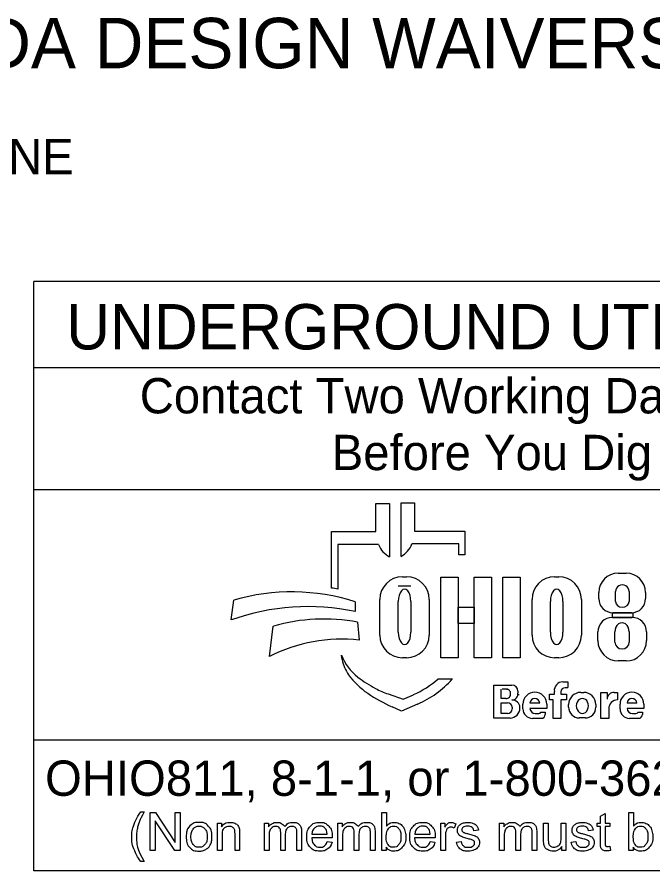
# Model space of a CAD drawing. Extents: x 0 to 34, y 0 to 22.
# Drawn here: x 2.311 to 4.831, y 2.143 to 5.529 of the extents above; entities that cross this region are included whole.
import ezdxf

# ---------------------------------------------------------------- set-up
doc = ezdxf.new("R2010")
doc.units = 0
doc.layers.add('SH_Data', color=7, linetype='Continuous')
doc.layers.add('SH_Text', color=7, linetype='Continuous')

msp = doc.modelspace()

# ---------------------------------------------------------------- linework, layer by layer
at = {"layer": 'SH_Data'}
for p, q in [((2.3775, 2.1428), (2.3775, 4.4803)), ((6.6275, 4.4803), (2.3775, 4.4803)), ((2.3775, 4.1387), (6.6275, 4.1387)), ((2.3775, 3.6553), (6.6275, 3.6553)), ((6.6275, 2.6607), (2.3775, 2.6607)), ((6.6275, 2.1428), (2.3775, 2.1428))]:
    msp.add_line(p, q, dxfattribs=at)
at = {"layer": 'SH_Text'}
for p, q in [((3.7335, 3.4883), (3.7335, 3.5998)), ((3.7335, 3.5998), (3.7872, 3.5998)), ((3.7872, 3.5998), (3.7872, 3.3877)), ((3.8329, 3.39), (3.8329, 3.6021)), ((3.8329, 3.6021), (3.8865, 3.6021)), ((3.8865, 3.6021), (3.8865, 3.4906)), ((3.5576, 3.2644), (3.5576, 3.4883)), ((3.5576, 3.4883), (3.7335, 3.4883)), ((3.8865, 3.4906), (4.0857, 3.4906)), ((4.0857, 3.4906), (4.0857, 3.3968)), ((3.5828, 3.4369), (3.5828, 3.26)), ((3.7439, 3.4369), (3.5828, 3.4369)), ((4.0625, 3.4392), (3.8761, 3.4392)), ((4.0625, 3.3968), (4.0625, 3.4392)), ((4.0857, 3.3968), (4.0625, 3.3968)), ((4.6931, 3.3231), (4.7258, 3.3231)), ((3.8385, 3.3091), (3.8551, 3.3091)), ((4.4416, 3.3091), (4.4581, 3.3091)), ((3.8718, 3.2721), (3.822, 3.2721)), ((4.683, 3.2111), (4.683, 3.2504)), ((4.7371, 3.2504), (4.7371, 3.2111)), ((3.7491, 3.0776), (3.7491, 3.2196)), ((3.9445, 3.2196), (3.9445, 3.0776)), ((4.3521, 3.0776), (4.3521, 3.2196)), ((4.5476, 3.2196), (4.5476, 3.0776)), ((4.6168, 3.2225), (4.6168, 3.2468)), ((4.8022, 3.2468), (4.8022, 3.2225)), ((3.1602, 3.1381), (3.1696, 3.2162)), ((3.6509, 3.2097), (3.6509, 3.1709)), ((3.822, 3.089), (3.822, 3.2114)), ((3.8718, 3.2114), (3.8718, 3.089)), ((4.425, 3.089), (4.425, 3.2114)), ((4.4748, 3.2114), (4.4748, 3.089)), ((4.7462, 3.1665), (4.6728, 3.1665)), ((3.6608, 3.1291), (3.6671, 3.0582)), ((4.671, 3.1482), (4.7483, 3.1482)), ((3.312, 2.9936), (3.3267, 3.1137)), ((4.6131, 3.0563), (4.6131, 3.0903)), ((4.6806, 3.0503), (4.6806, 3.0912)), ((4.7374, 3.0912), (4.7374, 3.0503)), ((4.8062, 3.0903), (4.8062, 3.0563)), ((3.5997, 2.9807), (3.5967, 2.9986)), ((3.8551, 2.9882), (3.8385, 2.9882)), ((4.4581, 2.9882), (4.4416, 2.9882)), ((4.7252, 2.9753), (4.6941, 2.9753)), ((3.98, 2.9048), (4.0375, 2.9048)), ((4.2013, 2.749), (4.2013, 2.8798)), ((4.2013, 2.8798), (4.2725, 2.8798)), ((4.4739, 2.8926), (4.4934, 2.8926)), ((4.4934, 2.8926), (4.4934, 2.8696)), ((3.7816, 2.8444), (3.841, 2.8239)), ((4.2293, 2.8263), (4.2293, 2.8632)), ((4.2545, 2.8632), (4.2332, 2.8632)), ((4.2963, 2.856), (4.2963, 2.8481)), ((4.4213, 2.8212), (4.4213, 2.8442)), ((4.4213, 2.8442), (4.4406, 2.8442)), ((4.4406, 2.8442), (4.4406, 2.8546)), ((4.4667, 2.8526), (4.4667, 2.8442)), ((4.4667, 2.8442), (4.4883, 2.8442)), ((4.4934, 2.8691), (4.4832, 2.8691)), ((4.4883, 2.8442), (4.4883, 2.8212)), ((4.5451, 2.8508), (4.5573, 2.8508)), ((4.6254, 2.7478), (4.6254, 2.8505)), ((4.6254, 2.8505), (4.6499, 2.8505)), ((4.6499, 2.8505), (4.6499, 2.8237)), ((4.6772, 2.8505), (4.691, 2.8505)), ((4.691, 2.8505), (4.691, 2.8209)), ((3.841, 2.8239), (3.8821, 2.8417)), ((4.2487, 2.8263), (4.2293, 2.8263)), ((4.4362, 2.8212), (4.4213, 2.8212)), ((4.4362, 2.7478), (4.4362, 2.8212)), ((4.4883, 2.8212), (4.4667, 2.8212)), ((4.4667, 2.8212), (4.4667, 2.7478)), ((3.835, 2.7769), (3.7976, 2.7934)), ((3.8983, 2.8044), (3.835, 2.7769)), ((4.2293, 2.7669), (4.2293, 2.8097)), ((4.2293, 2.8097), (4.2548, 2.8097)), ((4.2729, 2.7916), (4.2729, 2.7853)), ((4.3043, 2.7887), (4.3043, 2.7884)), ((4.3159, 2.7858), (4.3159, 2.8042)), ((4.3824, 2.8082), (4.3439, 2.8082)), ((4.4104, 2.7866), (4.344, 2.7866)), ((4.4104, 2.8042), (4.4104, 2.7866)), ((4.4973, 2.7922), (4.4973, 2.8029)), ((4.6051, 2.8029), (4.6051, 2.7922)), ((4.6559, 2.786), (4.6559, 2.7478)), ((4.7008, 2.7858), (4.7008, 2.8042)), ((4.7674, 2.8082), (4.7288, 2.8082)), ((4.7953, 2.7866), (4.7289, 2.7866)), ((4.7953, 2.8042), (4.7953, 2.7866)), ((4.265, 2.749), (4.2013, 2.749)), ((4.2546, 2.7669), (4.2293, 2.7669)), ((4.3892, 2.7478), (4.3538, 2.7478)), ((4.3649, 2.7673), (4.379, 2.7673)), ((4.3876, 2.7729), (4.4045, 2.7729)), ((4.4045, 2.7729), (4.4045, 2.7631)), ((4.4667, 2.7478), (4.4362, 2.7478)), ((4.5623, 2.7494), (4.5401, 2.7494)), ((4.6559, 2.7478), (4.6254, 2.7478)), ((4.7742, 2.7478), (4.7388, 2.7478)), ((4.7498, 2.7673), (4.7639, 2.7673)), ((4.7725, 2.7729), (4.7894, 2.7729)), ((4.7894, 2.7729), (4.7894, 2.7631))]:
    msp.add_line(p, q, dxfattribs=at)
for points in [[(3.991, 3.3081), (4.0589, 3.3081), (4.0589, 2.9881), (3.991, 2.9881)], [(4.1231, 3.3081), (4.1911, 3.3081), (4.1911, 2.9881), (4.1231, 2.9881)], [(4.2364, 3.3081), (4.3052, 3.3081), (4.3052, 2.9881), (4.2364, 2.9881)], [(4.0589, 3.1882), (4.1231, 3.1882), (4.1231, 3.1242), (4.0589, 3.1242)], [(4.6706, 3.1665), (4.7523, 3.1665), (4.7523, 3.1481), (4.6706, 3.1481)]]:
    msp.add_lwpolyline(points, close=True, dxfattribs=at)
for points in [[(2.8021, 2.3766), (2.8153, 2.3766)], [(2.8389, 2.2239), (2.8389, 2.3741), (2.8592, 2.3741), (2.9382, 2.2561), (2.9382, 2.3741), (2.9572, 2.3741), (2.9572, 2.2239), (2.9369, 2.2239), (2.8579, 2.3419), (2.8579, 2.2239), (2.8389, 2.2239)], [(3.7743, 2.2239), (3.7573, 2.2239), (3.7573, 2.3741), (3.7757, 2.3741), (3.7757, 2.3206)], [(4.6233, 2.2558), (4.6233, 2.3185), (4.6097, 2.3185), (4.6097, 2.3328), (4.6233, 2.3328), (4.6233, 2.3597), (4.6417, 2.3708), (4.6417, 2.3328), (4.6601, 2.3328), (4.6601, 2.3185), (4.6417, 2.3185), (4.6417, 2.2547)], [(4.7534, 2.2239), (4.7363, 2.2239), (4.7363, 2.3741), (4.7548, 2.3741), (4.7548, 2.3206)], [(3.1048, 2.2239), (3.1048, 2.3328), (3.1214, 2.3328), (3.1214, 2.3173)], [(3.2912, 2.2239), (3.2912, 2.3328), (3.3077, 2.3328), (3.3077, 2.3174)], [(3.5826, 2.2239), (3.5826, 2.3328), (3.5991, 2.3328), (3.5991, 2.3174)], [(3.9904, 2.2239), (3.9904, 2.3328), (4.007, 2.3328), (4.007, 2.3163)], [(4.0495, 2.3293), (4.043, 2.3122)], [(4.1394, 2.3046), (4.1213, 2.3022)], [(4.2236, 2.2239), (4.2236, 2.3328), (4.2401, 2.3328), (4.2401, 2.3174)], [(4.3979, 2.2654), (4.3979, 2.3328), (4.4164, 2.3328), (4.4164, 2.2724)], [(4.4676, 2.2745), (4.4676, 2.3328), (4.4861, 2.3328), (4.4861, 2.2239), (4.4696, 2.2239)], [(4.594, 2.3046), (4.5759, 2.3022)], [(3.1233, 2.2833), (3.1233, 2.2239), (3.1048, 2.2239)], [(3.1932, 2.2908), (3.1932, 2.2239), (3.1748, 2.2239), (3.1748, 2.2901)], [(3.3097, 2.2803), (3.3097, 2.2239), (3.2912, 2.2239)], [(3.3743, 2.2871), (3.3743, 2.2239), (3.3559, 2.2239), (3.3559, 2.2946)], [(3.4388, 2.2986), (3.4388, 2.2239), (3.4203, 2.2239), (3.4203, 2.2924)], [(3.56, 2.2736), (3.4788, 2.2736)], [(3.4799, 2.2887), (3.5406, 2.2887)], [(3.601, 2.2803), (3.601, 2.2239), (3.5826, 2.2239)], [(3.6657, 2.2871), (3.6657, 2.2239), (3.6473, 2.2239), (3.6473, 2.2946)], [(3.7301, 2.2986), (3.7301, 2.2239), (3.7117, 2.2239), (3.7117, 2.2924)], [(3.968, 2.2736), (3.8868, 2.2736)], [(3.8879, 2.2887), (3.9486, 2.2887)], [(4.0088, 2.2809), (4.0088, 2.2239), (3.9904, 2.2239)], [(4.242, 2.2803), (4.242, 2.2239), (4.2236, 2.2239)], [(4.3067, 2.2871), (4.3067, 2.2239), (4.2883, 2.2239), (4.2883, 2.2946)], [(4.3711, 2.2986), (4.3711, 2.2239), (4.3527, 2.2239), (4.3527, 2.2924)], [(3.5404, 2.2591), (3.5595, 2.2567)], [(3.7743, 2.2375), (3.7743, 2.2239)], [(3.9484, 2.2591), (3.9675, 2.2567)], [(4.053, 2.2564), (4.0712, 2.2593)], [(4.4696, 2.2239), (4.4696, 2.24)], [(4.5076, 2.2564), (4.5258, 2.2593)], [(4.6601, 2.2404), (4.6628, 2.2241)], [(4.7534, 2.2375), (4.7534, 2.2239)], [(2.8153, 2.1798), (2.8021, 2.1798)]]:
    msp.add_lwpolyline(points, dxfattribs=at)
for centre, radius, start, end in [((3.8353, 3.4736), 0.0985, 201.9296, 240.7469), ((3.7847, 3.476), 0.0985, 299.2531, 338.0704), ((4.6931, 3.2468), 0.0763, 90, 180), ((4.7258, 3.2468), 0.0763, 0, 90), ((3.8385, 3.2196), 0.0895, 90, 180), ((3.8551, 3.2196), 0.0895, 0, 90), ((4.4416, 3.2196), 0.0895, 90, 180), ((4.4581, 3.2196), 0.0895, 0, 90), ((3.4295, 2.4554), 0.8191, 79.2074, 81.0007), ((3.3997, 2.4302), 0.8191, 72.1402, 106.3144), ((4.6728, 3.2225), 0.056, 180, 270), ((4.7462, 3.2225), 0.056, 270, 0), ((3.4628, 2.2991), 0.8919, 77.8238, 109.8274), ((3.5267, 2.4094), 0.7322, 79.44, 105.8467), ((4.671, 3.0903), 0.0579, 90, 180), ((4.7483, 3.0903), 0.0579, 0, 90), ((3.5987, 2.4262), 0.6357, 83.8248, 116.8021), ((3.8385, 3.0776), 0.0895, 180, 270), ((3.8551, 3.0776), 0.0895, 270, 0), ((4.4416, 3.0776), 0.0895, 180, 270), ((4.4581, 3.0776), 0.0895, 270, 0), ((4.6941, 3.0563), 0.081, 180, 270), ((4.7252, 3.0563), 0.081, 270, 0), ((3.7841, 3.0707), 0.2008, 201.0457, 232.5314), ((3.741, 3.0048), 0.1433, 189.6817, 216.0884), ((3.8747, 3.1022), 0.3088, 216.0884, 235.7167), ((3.9766, 3.3219), 0.5173, 232.5314, 241.794), ((3.7387, 3.1722), 0.3602, 293.4582, 312.0712), ((3.7387, 3.1722), 0.401, 293.4582, 317.8286), ((4.2725, 2.856), 0.0238, 0, 90), ((4.4739, 2.859), 0.0335, 90, 187.5187), ((4.0412, 3.3465), 0.6044, 235.7167, 246.2325), ((3.8914, 3.1631), 0.3371, 241.794, 250.9821), ((4.2487, 2.845), 0.0187, 270, 2.0582), ((4.2505, 2.8463), 0.0169, 357.8325, 90), ((4.2721, 2.8453), 0.0243, 270, 6.6529), ((4.3631, 2.8042), 0.0473, 0, 180), ((4.4832, 2.8526), 0.0165, 90, 180), ((4.5451, 2.8029), 0.0478, 90, 180), ((4.5573, 2.8029), 0.0478, 0, 90), ((4.6768, 2.8237), 0.0269, 89.2449, 180), ((4.7481, 2.8042), 0.0473, 0, 180), ((4.2722, 2.7889), 0.0321, 4.0748, 90), ((4.2827, 2.8438), 0.0175, 347.4023, 0), ((4.3632, 2.8072), 0.0193, 2.9632, 177.0368), ((4.6908, 2.786), 0.0349, 89.6033, 180), ((4.7481, 2.8072), 0.0193, 2.9632, 177.0368), ((4.2546, 2.7853), 0.0184, 270, 0), ((4.2548, 2.7916), 0.0181, 0, 90), ((4.265, 2.7884), 0.0393, 270, 0), ((4.2714, 2.7887), 0.033, 0, 11.7502), ((4.3538, 2.7858), 0.038, 180, 270), ((4.3649, 2.7883), 0.021, 184.827, 270), ((4.5401, 2.7922), 0.0428, 180, 270), ((4.5623, 2.7922), 0.0428, 270, 0), ((4.7388, 2.7858), 0.038, 180, 270), ((4.7498, 2.7883), 0.021, 184.827, 270), ((4.379, 2.7767), 0.00938, 270, 335.9979), ((4.3892, 2.7631), 0.0152, 270, 0), ((4.7639, 2.7767), 0.00938, 270, 335.9979), ((4.7742, 2.7631), 0.0152, 270, 0)]:
    msp.add_arc(centre, radius, start, end, dxfattribs=at)
for centre, major_axis, ratio, start_param, end_param in [((3.8469, 3.2114), (0, 0.0484), 0.514403, 4.712389, 7.853982), ((4.4499, 3.2114), (0, 0.0484), 0.514403, 4.712389, 7.853982), ((4.71, 3.2504), (0.0271, 0), 0.969373, 0, 3.141593), ((4.71, 3.2111), (0.0271, 0), 0.818453, 3.141593, 6.283185), ((4.709, 3.0912), (0, 0.0358), 0.794529, 4.712389, 7.853982), ((3.8469, 3.089), (0, 0.0484), 0.514403, 1.570796, 4.712389), ((4.4499, 3.089), (0, 0.0484), 0.514403, 1.570796, 4.712389), ((4.709, 3.0503), (0.0284, 0), 0.959837, 3.141593, 6.283185), ((4.5517, 2.7976), (0, 0.029), 0.832186, 4.712389, 7.853982), ((4.5517, 2.7976), (0, 0.0302), 0.797287, 1.570796, 4.712389)]:
    msp.add_ellipse(centre, major_axis=major_axis, ratio=ratio, start_param=start_param, end_param=end_param, dxfattribs=at)
for points in [[(2.8021, 2.1798), (2.7869, 2.199), (2.7763, 2.2248), (2.7657, 2.2506), (2.7657, 2.2783), (2.7657, 2.3026), (2.7736, 2.325), (2.7829, 2.3509), (2.8021, 2.3766)], [(2.8153, 2.3766), (2.8029, 2.3553), (2.7989, 2.3462), (2.7927, 2.332), (2.7891, 2.3167), (2.7847, 2.2975), (2.7847, 2.2782), (2.7847, 2.2289), (2.8153, 2.1798)], [(2.9814, 2.2783), (2.9814, 2.3085), (2.9981, 2.3231), (3.0122, 2.3352), (3.0323, 2.3352), (3.0547, 2.3352), (3.069, 2.3205), (3.0832, 2.3058), (3.0832, 2.2799), (3.0832, 2.2589), (3.0769, 2.2469), (3.0706, 2.2348), (3.0586, 2.2282), (3.0466, 2.2215), (3.0323, 2.2215), (3.0095, 2.2215), (2.9954, 2.2362), (2.9814, 2.2508), (2.9814, 2.2783)], [(3.0003, 2.2783), (3.0003, 2.2574), (3.0094, 2.247), (3.0185, 2.2366), (3.0323, 2.2366), (3.046, 2.2366), (3.0551, 2.2471), (3.0642, 2.2575), (3.0642, 2.279), (3.0642, 2.2991), (3.0551, 2.3095), (3.0459, 2.3199), (3.0323, 2.3199), (3.0185, 2.3199), (3.0094, 2.3096), (3.0003, 2.2992), (3.0003, 2.2783)], [(3.1214, 2.3173), (3.1334, 2.3352), (3.156, 2.3352), (3.1659, 2.3352), (3.1741, 2.3316), (3.1823, 2.3281), (3.1864, 2.3224), (3.1905, 2.3166), (3.1922, 2.3087), (3.1932, 2.3036), (3.1932, 2.2908)], [(3.1748, 2.2901), (3.1748, 2.3013), (3.1726, 2.3069), (3.1705, 2.3125), (3.165, 2.3158), (3.1595, 2.3191), (3.1521, 2.3191), (3.1404, 2.3191), (3.1318, 2.3117), (3.1233, 2.3042), (3.1233, 2.2833)], [(3.3077, 2.3174), (3.3128, 2.3254), (3.3214, 2.3303), (3.3299, 2.3352), (3.3407, 2.3352), (3.3528, 2.3352), (3.3606, 2.3301), (3.3683, 2.3251), (3.3715, 2.3161), (3.3844, 2.3352), (3.4051, 2.3352), (3.4213, 2.3352), (3.43, 2.3262), (3.4388, 2.3172), (3.4388, 2.2986)], [(3.3559, 2.2946), (3.3559, 2.3069), (3.3514, 2.313), (3.3469, 2.3191), (3.3366, 2.3191), (3.3288, 2.3191), (3.3222, 2.315), (3.3156, 2.311), (3.3126, 2.3031), (3.3097, 2.2952), (3.3097, 2.2803)], [(3.4203, 2.2924), (3.4203, 2.3035), (3.4185, 2.3083), (3.4168, 2.3132), (3.412, 2.3162), (3.4073, 2.3191), (3.401, 2.3191), (3.3895, 2.3191), (3.3819, 2.3115), (3.3743, 2.3039), (3.3743, 2.2871)], [(3.5595, 2.2567), (3.555, 2.24), (3.5428, 2.2307), (3.5306, 2.2215), (3.5117, 2.2215), (3.4878, 2.2215), (3.4738, 2.2362), (3.4598, 2.2509), (3.4598, 2.2774), (3.4598, 2.3049), (3.474, 2.32), (3.4881, 2.3352), (3.5106, 2.3352), (3.5324, 2.3352), (3.5463, 2.3203), (3.5601, 2.3055), (3.5601, 2.2785), (3.5601, 2.2769), (3.56, 2.2736)], [(3.5406, 2.2887), (3.5394, 2.3025), (3.5337, 2.3094), (3.5249, 2.3201), (3.5108, 2.3201), (3.4981, 2.3201), (3.4894, 2.3115), (3.4808, 2.303), (3.4799, 2.2887)], [(3.5991, 2.3174), (3.6042, 2.3254), (3.6127, 2.3303), (3.6212, 2.3352), (3.6321, 2.3352), (3.6442, 2.3352), (3.6519, 2.3301), (3.6597, 2.3251), (3.6628, 2.3161), (3.6758, 2.3352), (3.6965, 2.3352), (3.7127, 2.3352), (3.7214, 2.3262), (3.7301, 2.3172), (3.7301, 2.2986)], [(3.6473, 2.2946), (3.6473, 2.3069), (3.6428, 2.313), (3.6383, 2.3191), (3.628, 2.3191), (3.6202, 2.3191), (3.6136, 2.315), (3.607, 2.311), (3.604, 2.3031), (3.601, 2.2952), (3.601, 2.2803)], [(3.7117, 2.2924), (3.7117, 2.3035), (3.7099, 2.3083), (3.7081, 2.3132), (3.7034, 2.3162), (3.6987, 2.3191), (3.6923, 2.3191), (3.6809, 2.3191), (3.6733, 2.3115), (3.6657, 2.3039), (3.6657, 2.2871)], [(3.7741, 2.2792), (3.7741, 2.2596), (3.7794, 2.2509), (3.7881, 2.2366), (3.8029, 2.2366), (3.815, 2.2366), (3.8238, 2.2471), (3.8326, 2.2576), (3.8326, 2.2784), (3.8326, 2.2998), (3.8241, 2.3099), (3.8157, 2.3201), (3.8038, 2.3201), (3.7917, 2.3201), (3.7829, 2.3096), (3.7741, 2.299), (3.7741, 2.2792)], [(3.7757, 2.3206), (3.7874, 2.3352), (3.8055, 2.3352), (3.8155, 2.3352), (3.8245, 2.3311), (3.8335, 2.3271), (3.8392, 2.3198), (3.845, 2.3124), (3.8483, 2.3021), (3.8516, 2.2918), (3.8516, 2.28), (3.8516, 2.252), (3.8378, 2.2368), (3.8239, 2.2215), (3.8046, 2.2215), (3.7853, 2.2215), (3.7743, 2.2375)], [(3.9675, 2.2567), (3.963, 2.24), (3.9508, 2.2307), (3.9386, 2.2215), (3.9196, 2.2215), (3.8958, 2.2215), (3.8818, 2.2362), (3.8678, 2.2509), (3.8678, 2.2774), (3.8678, 2.3049), (3.882, 2.32), (3.8961, 2.3352), (3.9186, 2.3352), (3.9404, 2.3352), (3.9543, 2.3203), (3.9681, 2.3055), (3.9681, 2.2785), (3.9681, 2.2769), (3.968, 2.2736)], [(3.9486, 2.2887), (3.9474, 2.3025), (3.9417, 2.3094), (3.9328, 2.3201), (3.9188, 2.3201), (3.9061, 2.3201), (3.8974, 2.3115), (3.8888, 2.303), (3.8879, 2.2887)], [(4.007, 2.3163), (4.0133, 2.3278), (4.0187, 2.3315), (4.0241, 2.3352), (4.0305, 2.3352), (4.0398, 2.3352), (4.0495, 2.3293)], [(4.043, 2.3122), (4.0363, 2.3162), (4.0295, 2.3162), (4.0235, 2.3162), (4.0187, 2.3125), (4.0139, 2.3089), (4.0119, 2.3024), (4.0088, 2.2926), (4.0088, 2.2809)], [(4.1213, 2.3022), (4.1201, 2.3106), (4.1142, 2.3153), (4.1083, 2.3201), (4.0975, 2.3201), (4.0848, 2.3201), (4.0794, 2.3159), (4.0739, 2.3116), (4.0739, 2.306), (4.0739, 2.3024), (4.0762, 2.2995), (4.0785, 2.2966), (4.0833, 2.2946), (4.086, 2.2936), (4.0996, 2.2899), (4.1192, 2.2847), (4.1269, 2.2813), (4.1347, 2.278), (4.1391, 2.2717), (4.1435, 2.2653), (4.1435, 2.2559), (4.1435, 2.2467), (4.1381, 2.2386), (4.1327, 2.2304), (4.1226, 2.226), (4.1124, 2.2215), (4.0996, 2.2215), (4.0784, 2.2215), (4.0672, 2.2303), (4.0561, 2.2391), (4.053, 2.2564)], [(4.0712, 2.2593), (4.0727, 2.2483), (4.0798, 2.2425), (4.0868, 2.2366), (4.0995, 2.2366), (4.1122, 2.2366), (4.1184, 2.2418), (4.1245, 2.247), (4.1245, 2.254), (4.1245, 2.2602), (4.1191, 2.2638), (4.1153, 2.2663), (4.1002, 2.2701), (4.0799, 2.2752), (4.072, 2.2789), (4.0642, 2.2827), (4.0601, 2.2893), (4.0561, 2.2959), (4.0561, 2.3038), (4.0561, 2.3111), (4.0594, 2.3173), (4.0628, 2.3235), (4.0685, 2.3276), (4.0728, 2.3308), (4.0803, 2.333), (4.0877, 2.3352), (4.0962, 2.3352), (4.109, 2.3352), (4.1187, 2.3315), (4.1284, 2.3278), (4.133, 2.3215), (4.1377, 2.3152), (4.1394, 2.3046)], [(4.2401, 2.3174), (4.2452, 2.3254), (4.2537, 2.3303), (4.2622, 2.3352), (4.2731, 2.3352), (4.2852, 2.3352), (4.2929, 2.3301), (4.3007, 2.3251), (4.3038, 2.3161), (4.3168, 2.3352), (4.3375, 2.3352), (4.3537, 2.3352), (4.3624, 2.3262), (4.3711, 2.3172), (4.3711, 2.2986)], [(4.2883, 2.2946), (4.2883, 2.3069), (4.2838, 2.313), (4.2793, 2.3191), (4.269, 2.3191), (4.2612, 2.3191), (4.2546, 2.315), (4.248, 2.311), (4.245, 2.3031), (4.242, 2.2952), (4.242, 2.2803)], [(4.3527, 2.2924), (4.3527, 2.3035), (4.3509, 2.3083), (4.3491, 2.3132), (4.3444, 2.3162), (4.3397, 2.3191), (4.3333, 2.3191), (4.3219, 2.3191), (4.3143, 2.3115), (4.3067, 2.3039), (4.3067, 2.2871)], [(4.5759, 2.3022), (4.5747, 2.3106), (4.5688, 2.3153), (4.5629, 2.3201), (4.5521, 2.3201), (4.5394, 2.3201), (4.5339, 2.3159), (4.5285, 2.3116), (4.5285, 2.306), (4.5285, 2.3024), (4.5308, 2.2995), (4.533, 2.2966), (4.5378, 2.2946), (4.5406, 2.2936), (4.5542, 2.2899), (4.5737, 2.2847), (4.5815, 2.2813), (4.5893, 2.278), (4.5937, 2.2717), (4.5981, 2.2653), (4.5981, 2.2559), (4.5981, 2.2467), (4.5927, 2.2386), (4.5873, 2.2304), (4.5772, 2.226), (4.567, 2.2215), (4.5542, 2.2215), (4.5329, 2.2215), (4.5218, 2.2303), (4.5107, 2.2391), (4.5076, 2.2564)], [(4.5258, 2.2593), (4.5273, 2.2483), (4.5343, 2.2425), (4.5414, 2.2366), (4.554, 2.2366), (4.5668, 2.2366), (4.5729, 2.2418), (4.5791, 2.247), (4.5791, 2.254), (4.5791, 2.2602), (4.5736, 2.2638), (4.5698, 2.2663), (4.5548, 2.2701), (4.5345, 2.2752), (4.5266, 2.2789), (4.5188, 2.2827), (4.5147, 2.2893), (4.5107, 2.2959), (4.5107, 2.3038), (4.5107, 2.3111), (4.514, 2.3173), (4.5173, 2.3235), (4.5231, 2.3276), (4.5274, 2.3308), (4.5348, 2.333), (4.5423, 2.3352), (4.5508, 2.3352), (4.5636, 2.3352), (4.5733, 2.3315), (4.583, 2.3278), (4.5876, 2.3215), (4.5922, 2.3152), (4.594, 2.3046)], [(4.7532, 2.2792), (4.7532, 2.2596), (4.7585, 2.2509), (4.7672, 2.2366), (4.782, 2.2366), (4.7941, 2.2366), (4.8029, 2.2471), (4.8116, 2.2576), (4.8116, 2.2784), (4.8116, 2.2998), (4.8032, 2.3099), (4.7948, 2.3201), (4.7828, 2.3201), (4.7708, 2.3201), (4.762, 2.3096), (4.7532, 2.299), (4.7532, 2.2792)], [(4.7548, 2.3206), (4.7664, 2.3352), (4.7846, 2.3352), (4.7946, 2.3352), (4.8036, 2.3311), (4.8125, 2.3271), (4.8183, 2.3198), (4.8241, 2.3124), (4.8274, 2.3021), (4.8306, 2.2918), (4.8306, 2.28), (4.8306, 2.252), (4.8168, 2.2368), (4.803, 2.2215), (4.7836, 2.2215), (4.7644, 2.2215), (4.7534, 2.2375)], [(3.4788, 2.2736), (3.4799, 2.2557), (3.489, 2.2462), (3.4981, 2.2366), (3.5117, 2.2366), (3.5219, 2.2366), (3.5291, 2.242), (3.5362, 2.2473), (3.5404, 2.2591)], [(3.8868, 2.2736), (3.8879, 2.2557), (3.897, 2.2462), (3.9061, 2.2366), (3.9197, 2.2366), (3.9299, 2.2366), (3.937, 2.242), (3.9442, 2.2473), (3.9484, 2.2591)], [(4.4164, 2.2724), (4.4164, 2.258), (4.4175, 2.253), (4.4192, 2.2457), (4.4249, 2.2416), (4.4305, 2.2374), (4.4388, 2.2374), (4.4471, 2.2374), (4.4543, 2.2417), (4.4616, 2.2459), (4.4646, 2.2533), (4.4676, 2.2606), (4.4676, 2.2745)], [(4.4696, 2.24), (4.4569, 2.2215), (4.4351, 2.2215), (4.4255, 2.2215), (4.4171, 2.2252), (4.4088, 2.2289), (4.4047, 2.2345), (4.4007, 2.2401), (4.3991, 2.2482), (4.3979, 2.2536), (4.3979, 2.2654)], [(4.6628, 2.2241), (4.655, 2.2224), (4.6488, 2.2224), (4.6388, 2.2224), (4.6333, 2.2256), (4.6278, 2.2288), (4.6255, 2.234), (4.6233, 2.2392), (4.6233, 2.2558)], [(4.6417, 2.2547), (4.6417, 2.2468), (4.6427, 2.2445), (4.6436, 2.2423), (4.6458, 2.2409), (4.648, 2.2396), (4.6521, 2.2396), (4.6551, 2.2396), (4.6601, 2.2404)]]:
    msp.add_open_spline(points, degree=3, dxfattribs=at)

# ---------------------------------------------------------------- texts
for s, height, p in [('ADA DESIGN WAIVERS', 0.2, (1.9944, 5.3256)), ('NONE', 0.14, (1.9944, 4.9056)), ('UNDERGROUND UTILITIES', 0.18, (2.5057, 4.2106)), ('Contact Two Working Days', 0.14, (2.7972, 3.9571)), ('Before You Dig', 0.14, (3.5583, 3.7321)), ('OHIO811, 8-1-1, or 1-800-362-2764', 0.14, (2.422, 2.4406))]:
    msp.add_text(s, height=height, dxfattribs=at).set_placement(p)

doc.saveas('drawing.dxf')
